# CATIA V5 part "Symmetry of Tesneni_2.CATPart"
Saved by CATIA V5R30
Part number: Symmetry of Tesneni_2
Bounding box of the stored display mesh (mm): x 0 to 1.2, y -6 to 6, z -6 to 6
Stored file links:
  E:\Bakalarka\Model\Forma_v7\Symmetry of Tesneni_2.CATPart
  E:\Bakalarka\Model\Forma_v7\Tesneni.CATPart
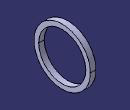
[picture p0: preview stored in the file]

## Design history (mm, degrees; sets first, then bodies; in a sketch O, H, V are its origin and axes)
Body1 (main body)
  Body2 "Body from original PartBody"
    Solid1: linked copy from another document
  Assemble1: tool Body2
